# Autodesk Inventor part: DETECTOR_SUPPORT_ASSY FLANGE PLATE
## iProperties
Shininess: 64.0
Length Units: 11272
Angle Units: 11279
Time Units: 11290
Mass Units: 11286
Length Display Precision: 3
Angle Display Precision: 2
Compacted: True
Part Number: DETECTOR_SUPPORT_ASSY FLANGE PLATE
Document SubType Name: Modeling
Created: 2004-08
Designer: John Blackburn
Material: ALUMINUM
Manufacturer: Standard
Standards Organization: Custom
Density: 0.0
Volumn: 0.0
Area: 0.0
PropertySet Name: Model Information
Control State: 0
Master: False
Checked Out: False
Author: John Blackburn
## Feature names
1. ExtrusionBlind1
2. AM_HOLE_0301DE_1 [Hole]
3. Hole1
4. Hole2
5. Hole3
